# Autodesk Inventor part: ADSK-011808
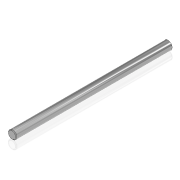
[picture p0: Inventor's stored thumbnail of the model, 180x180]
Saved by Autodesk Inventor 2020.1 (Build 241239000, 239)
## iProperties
Created: 1999-12
Part Number: ADSK-011808
Material: Acier (alliage faible hypertrempé)
Description: SLIDE SHAFT_SD22x4
Document SubType Name: Modeling
Designer: glanglot
Density: 7.84 g/cm^3
Appearance: Chrom - poliert
Mass: 113.225 g
Surface Area: 59.2218 cm^2
Volume: 14.442 cm^3
Control State: 0
Master: False
Checked Out: False
Shininess: 0.0
Length Units: 11269
Angle Units: 11279
Time Units: 11290
Mass Units: 11283
Length Display Precision: 3
Angle Display Precision: 2
Compacted: True
Dimensions: 10x10x184 mm
Mass: 0,113 kg
Density: 0.0
Volumn: 0.0
Area: 0.0
PropertySet Name: Model Information
Author: glanglot
Revision Number: -
Title: SLIDE SHAFT_SD22x4
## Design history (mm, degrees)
node "Solide1"
  node "Extrusion1" dims "d1" = 184, "d2" = 0
  node "Chamfer1" dims "d3" = 0.79375, "d4" = 0.79375, "d5" = 45 deg
sketch "Sketch1"
  geometry: C1 r 5 at (0, 0); 1 further point
  constraints: 1 centre point, 1 coincident
  dimensions: "d0" = 10 diameter of C1
node "Corps solides"
node "Corps surfaciques"
